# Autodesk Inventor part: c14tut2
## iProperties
Created: 2002-04
Part Number: c14tut2
Document SubType Name: Sheet Metal
Control State: 0
Master: False
Checked Out: False
Shininess: 77.0
Angle Display Precision: 2
Document Length Units: 11269
Document Angle Units: 11279
Document Time Units: 11290
Document Mass Units: 11283
Document Length Units Precision: 3
Document Angle Units Precision: 2
Density: 0.0
Volumn: 0.0
Area: 0.0
PropertySet Name: Model Information
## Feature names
1. Hole2
2. Rectangular Pattern1
3. Mirror2
4. Corner Round3
5. Plate1
6. Plate2
7. Bend1
8. Plate3
9. Bend2
10. Plate5
11. Bend4
12. FlatPatternExtrusion1
